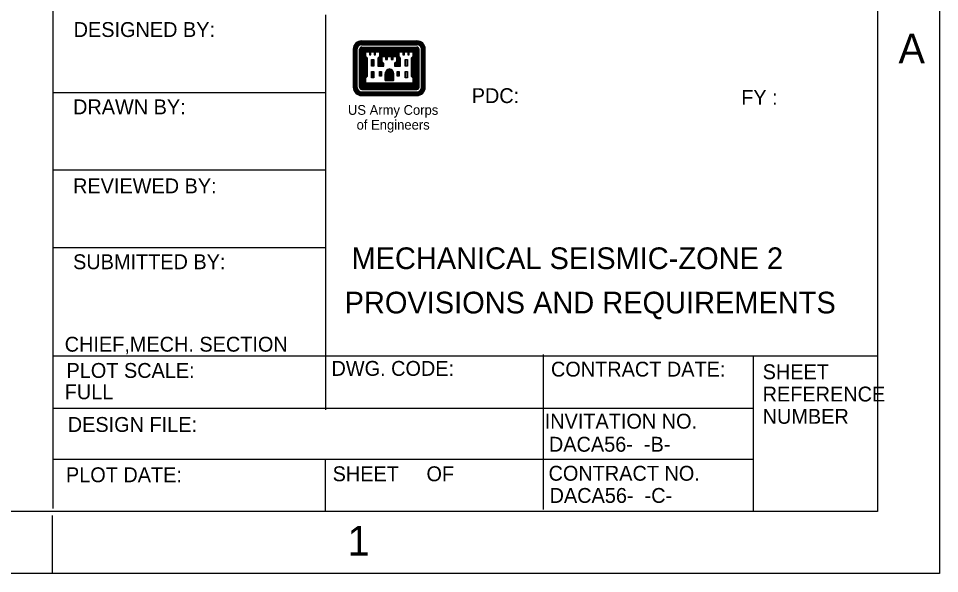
# Model space of a CAD drawing. Extents: x 9999.96 to 10005.26, y 9999.88 to 10002.38.
# Drawn here: x 10002.841 to 10003.46, y 9999.885 to 10000.258 of the extents above; entities that cross this region are included whole.
import ezdxf

# ---------------------------------------------------------------- set-up
doc = ezdxf.new("R2010")
doc.units = 0
for name, color, linetype in [('Level 1', 7, 'Continuous'), ('Level 3', 7, 'Continuous'), ('Level 50', 7, 'Continuous'), ('Level 6', 7, 'Continuous')]:
    doc.layers.add(name, color=color, linetype=linetype)

msp = doc.modelspace()

# ---------------------------------------------------------------- linework, layer by layer
at = {"layer": 'Level 1'}
for p, q in [((10003.46033, 10002.38453), (10003.46033, 9999.88453)), ((10003.41867, 10002.34286), (10003.41867, 9999.9262)), ((10002.86401, 9999.92827), (10002.86401, 10000.35495)), ((10003.04708, 10000.26011), (10003.04708, 9999.9945)), ((10002.86401, 10000.20803), (10003.04708, 10000.20803)), ((10002.86401, 10000.15595), (10003.04708, 10000.15595)), ((10002.86401, 10000.10386), (10003.04708, 10000.10386)), ((10002.86401, 10000.03095), (10003.41867, 10000.03095)), ((10003.19381, 9999.92764), (10003.19381, 10000.0318)), ((10003.3352, 9999.92626), (10003.3352, 10000.03043)), ((10002.86401, 9999.99561), (10003.3352, 9999.99561)), ((10003.3352, 9999.9612), (10002.86401, 9999.9612)), ((10003.04708, 9999.92678), (10003.04708, 9999.96068)), ((10003.41867, 9999.9262), (10000.127, 9999.9262)), ((10002.8635, 9999.8845), (10002.8635, 9999.92348)), ((10003.46033, 9999.88453), (9999.96033, 9999.88453))]:
    msp.add_line(p, q, dxfattribs=at)
at = {"layer": 'Level 6'}
for p, q in [((10003.07063, 10000.23997), (10003.07063, 10000.24268)), ((10003.07135, 10000.24008), (10003.07135, 10000.24268)), ((10003.07152, 10000.24273), (10003.10871, 10000.24273)), ((10003.07203, 10000.24008), (10003.07203, 10000.24268)), ((10003.07276, 10000.24008), (10003.07276, 10000.24268)), ((10003.07344, 10000.24008), (10003.07344, 10000.24268)), ((10003.07417, 10000.24008), (10003.07417, 10000.24268)), ((10003.07484, 10000.24008), (10003.07484, 10000.24268)), ((10003.07557, 10000.24008), (10003.07557, 10000.24268)), ((10003.07624, 10000.24008), (10003.07624, 10000.24268)), ((10003.07697, 10000.24008), (10003.07697, 10000.24268)), ((10003.07765, 10000.24008), (10003.07765, 10000.24268)), ((10003.07838, 10000.24008), (10003.07838, 10000.24268)), ((10003.07905, 10000.24008), (10003.07905, 10000.24268)), ((10003.07978, 10000.24008), (10003.07978, 10000.24268)), ((10003.08045, 10000.24008), (10003.08045, 10000.24268)), ((10003.08118, 10000.24008), (10003.08118, 10000.24268)), ((10003.08185, 10000.24008), (10003.08185, 10000.24268)), ((10003.08258, 10000.24008), (10003.08258, 10000.24268)), ((10003.08326, 10000.24008), (10003.08326, 10000.24268)), ((10003.08399, 10000.24008), (10003.08399, 10000.24268)), ((10003.08466, 10000.24008), (10003.08466, 10000.24268)), ((10003.08539, 10000.24008), (10003.08539, 10000.24268)), ((10003.08606, 10000.24008), (10003.08606, 10000.24268)), ((10003.08679, 10000.24008), (10003.08679, 10000.24268)), ((10003.08747, 10000.24008), (10003.08747, 10000.24268)), ((10003.0882, 10000.24008), (10003.0882, 10000.24268)), ((10003.08888, 10000.24008), (10003.08888, 10000.24268)), ((10003.0896, 10000.24008), (10003.0896, 10000.24268)), ((10003.09028, 10000.24008), (10003.09028, 10000.24268)), ((10003.09101, 10000.24008), (10003.09101, 10000.24268)), ((10003.09169, 10000.24008), (10003.09169, 10000.24268)), ((10003.09242, 10000.24008), (10003.09242, 10000.24268)), ((10003.09309, 10000.24008), (10003.09309, 10000.24268)), ((10003.09381, 10000.24008), (10003.09381, 10000.24268)), ((10003.09449, 10000.24008), (10003.09449, 10000.24268)), ((10003.09522, 10000.24008), (10003.09522, 10000.24268)), ((10003.0959, 10000.24008), (10003.0959, 10000.24268)), ((10003.09663, 10000.24008), (10003.09663, 10000.24268)), ((10003.0973, 10000.24008), (10003.0973, 10000.24268)), ((10003.09802, 10000.24008), (10003.09802, 10000.24268)), ((10003.0987, 10000.24008), (10003.0987, 10000.24268)), ((10003.09943, 10000.24008), (10003.09943, 10000.24268)), ((10003.1001, 10000.24008), (10003.1001, 10000.24268)), ((10003.10083, 10000.24008), (10003.10083, 10000.24268)), ((10003.10151, 10000.24008), (10003.10151, 10000.24268)), ((10003.10224, 10000.24008), (10003.10224, 10000.24268)), ((10003.10291, 10000.24008), (10003.10291, 10000.24268)), ((10003.10365, 10000.24008), (10003.10365, 10000.24268)), ((10003.10431, 10000.24008), (10003.10431, 10000.24268)), ((10003.10505, 10000.24008), (10003.10505, 10000.24268)), ((10003.10572, 10000.24008), (10003.10572, 10000.24268)), ((10003.10646, 10000.24008), (10003.10646, 10000.24268)), ((10003.10713, 10000.24008), (10003.10713, 10000.24268)), ((10003.10786, 10000.24008), (10003.10786, 10000.24268)), ((10003.10853, 10000.24008), (10003.10853, 10000.24268)), ((10003.10927, 10000.24008), (10003.10927, 10000.24268)), ((10003.10994, 10000.23986), (10003.10994, 10000.24261)), ((10003.06591, 10000.2115), (10003.06591, 10000.23711)), ((10003.06642, 10000.2092), (10003.06642, 10000.23941)), ((10003.06714, 10000.20796), (10003.06714, 10000.24065)), ((10003.06781, 10000.20729), (10003.06781, 10000.24132)), ((10003.06854, 10000.23728), (10003.06854, 10000.24189)), ((10003.06854, 10000.21133), (10003.06854, 10000.23728)), ((10003.06922, 10000.23907), (10003.06922, 10000.24222)), ((10003.06995, 10000.23969), (10003.06995, 10000.2425)), ((10003.07011, 10000.2115), (10003.07011, 10000.23711)), ((10003.07063, 10000.21044), (10003.07063, 10000.23819)), ((10003.07135, 10000.24008), (10003.10888, 10000.24008)), ((10003.07135, 10000.21009), (10003.07135, 10000.23852)), ((10003.07152, 10000.23852), (10003.10871, 10000.23852)), ((10003.07203, 10000.21009), (10003.07203, 10000.23852)), ((10003.07276, 10000.21009), (10003.07276, 10000.23852)), ((10003.07344, 10000.21009), (10003.07344, 10000.23852)), ((10003.07417, 10000.21009), (10003.07417, 10000.23852)), ((10003.07484, 10000.23538), (10003.07484, 10000.23852)), ((10003.07557, 10000.23538), (10003.07557, 10000.23852)), ((10003.07624, 10000.23538), (10003.07624, 10000.23852)), ((10003.07697, 10000.23323), (10003.07697, 10000.23852)), ((10003.07765, 10000.23323), (10003.07765, 10000.23852)), ((10003.07838, 10000.23538), (10003.07838, 10000.23852)), ((10003.07905, 10000.23538), (10003.07905, 10000.23852)), ((10003.07978, 10000.23538), (10003.07978, 10000.23852)), ((10003.08045, 10000.23329), (10003.08045, 10000.23852)), ((10003.08118, 10000.23538), (10003.08118, 10000.23852)), ((10003.08185, 10000.23538), (10003.08185, 10000.23852)), ((10003.08258, 10000.23538), (10003.08258, 10000.23852)), ((10003.08326, 10000.23538), (10003.08326, 10000.23852)), ((10003.08399, 10000.22559), (10003.08399, 10000.23852)), ((10003.08466, 10000.22559), (10003.08466, 10000.23852)), ((10003.08539, 10000.23222), (10003.08539, 10000.23852)), ((10003.08606, 10000.23222), (10003.08606, 10000.23852)), ((10003.08679, 10000.23222), (10003.08679, 10000.23852)), ((10003.08747, 10000.23222), (10003.08747, 10000.23852)), ((10003.0882, 10000.23008), (10003.0882, 10000.23852)), ((10003.08888, 10000.23222), (10003.08888, 10000.23852)), ((10003.0896, 10000.23222), (10003.0896, 10000.23852)), ((10003.09028, 10000.23222), (10003.09028, 10000.23852)), ((10003.09101, 10000.23222), (10003.09101, 10000.23852)), ((10003.09169, 10000.23008), (10003.09169, 10000.23852)), ((10003.09242, 10000.23008), (10003.09242, 10000.23852)), ((10003.09309, 10000.23222), (10003.09309, 10000.23852)), ((10003.09381, 10000.23222), (10003.09381, 10000.23852)), ((10003.09381, 10000.23222), (10003.09381, 10000.23852)), ((10003.09449, 10000.23222), (10003.09449, 10000.23852)), ((10003.09522, 10000.22559), (10003.09522, 10000.23852)), ((10003.0959, 10000.22559), (10003.0959, 10000.23852)), ((10003.09663, 10000.22559), (10003.09663, 10000.23852)), ((10003.0973, 10000.23538), (10003.0973, 10000.23852)), ((10003.09802, 10000.23538), (10003.09802, 10000.23852)), ((10003.0987, 10000.23538), (10003.0987, 10000.23852)), ((10003.09943, 10000.23323), (10003.09943, 10000.23852)), ((10003.1001, 10000.23323), (10003.1001, 10000.23852)), ((10003.10083, 10000.23538), (10003.10083, 10000.23852)), ((10003.10157, 10000.23538), (10003.10157, 10000.23852)), ((10003.10224, 10000.23538), (10003.10224, 10000.23852)), ((10003.10291, 10000.23323), (10003.10291, 10000.23852)), ((10003.10365, 10000.23538), (10003.10365, 10000.23852)), ((10003.10431, 10000.23538), (10003.10431, 10000.23852)), ((10003.10505, 10000.23538), (10003.10505, 10000.23852)), ((10003.10572, 10000.23538), (10003.10572, 10000.23852)), ((10003.10646, 10000.21009), (10003.10646, 10000.23852)), ((10003.10713, 10000.21009), (10003.10713, 10000.23852)), ((10003.10786, 10000.21009), (10003.10786, 10000.23852)), ((10003.10853, 10000.21009), (10003.10853, 10000.23852)), ((10003.10927, 10000.21021), (10003.10927, 10000.23841)), ((10003.10994, 10000.21082), (10003.10994, 10000.23779)), ((10003.11011, 10000.2115), (10003.11011, 10000.23711)), ((10003.11068, 10000.23941), (10003.11068, 10000.2424)), ((10003.11133, 10000.23863), (10003.11133, 10000.24205)), ((10003.11168, 10000.21133), (10003.11168, 10000.23728)), ((10003.11207, 10000.20701), (10003.11207, 10000.2416)), ((10003.1128, 10000.20769), (10003.1128, 10000.24093)), ((10003.11348, 10000.20852), (10003.11348, 10000.24008)), ((10003.11421, 10000.21038), (10003.11421, 10000.23824)), ((10003.11432, 10000.2115), (10003.11432, 10000.23711)), ((10003.07433, 10000.23222), (10003.07433, 10000.23538)), ((10003.07433, 10000.23538), (10003.07669, 10000.23538)), ((10003.07433, 10000.23222), (10003.07433, 10000.23538)), ((10003.07433, 10000.23538), (10003.07669, 10000.23538)), ((10003.07541, 10000.23116), (10003.07433, 10000.23222)), ((10003.07541, 10000.23116), (10003.07433, 10000.23222)), ((10003.0749, 10000.21841), (10003.0749, 10000.23166)), ((10003.07541, 10000.21903), (10003.07541, 10000.23116)), ((10003.07541, 10000.21903), (10003.07541, 10000.23116)), ((10003.07669, 10000.23538), (10003.07669, 10000.23323)), ((10003.07669, 10000.23538), (10003.07669, 10000.23323)), ((10003.07669, 10000.23323), (10003.07776, 10000.23323)), ((10003.07669, 10000.23323), (10003.07776, 10000.23323)), ((10003.07776, 10000.23323), (10003.07776, 10000.23538)), ((10003.07776, 10000.23538), (10003.0799, 10000.23538)), ((10003.07776, 10000.23323), (10003.07776, 10000.23538)), ((10003.07776, 10000.23538), (10003.0799, 10000.23538)), ((10003.0799, 10000.23538), (10003.0799, 10000.23323)), ((10003.0799, 10000.23538), (10003.0799, 10000.23323)), ((10003.0799, 10000.23323), (10003.0809, 10000.23323)), ((10003.0799, 10000.23323), (10003.0809, 10000.23323)), ((10003.0809, 10000.23323), (10003.0809, 10000.23538)), ((10003.0809, 10000.23538), (10003.08354, 10000.23538)), ((10003.0809, 10000.23323), (10003.0809, 10000.23538)), ((10003.0809, 10000.23538), (10003.08354, 10000.23538)), ((10003.08354, 10000.23222), (10003.08247, 10000.23116)), ((10003.08354, 10000.23222), (10003.08247, 10000.23116)), ((10003.08247, 10000.23116), (10003.08247, 10000.22559)), ((10003.08247, 10000.23116), (10003.08247, 10000.22559)), ((10003.08258, 10000.22559), (10003.08258, 10000.23126)), ((10003.08331, 10000.22559), (10003.08331, 10000.232)), ((10003.08354, 10000.23538), (10003.08354, 10000.23222)), ((10003.08354, 10000.23538), (10003.08354, 10000.23222)), ((10003.08539, 10000.22852), (10003.08539, 10000.23222)), ((10003.08539, 10000.23222), (10003.08747, 10000.23222)), ((10003.08747, 10000.23222), (10003.08747, 10000.23008)), ((10003.08882, 10000.23008), (10003.08882, 10000.23222)), ((10003.08882, 10000.23222), (10003.09146, 10000.23222)), ((10003.09146, 10000.23222), (10003.09146, 10000.23008)), ((10003.09276, 10000.23008), (10003.09276, 10000.23222)), ((10003.09276, 10000.23222), (10003.09489, 10000.23222)), ((10003.09489, 10000.23222), (10003.09489, 10000.22852)), ((10003.09674, 10000.23222), (10003.09674, 10000.23538)), ((10003.09674, 10000.23538), (10003.09932, 10000.23538)), ((10003.09774, 10000.23116), (10003.09674, 10000.23222)), ((10003.09736, 10000.22559), (10003.09736, 10000.23154)), ((10003.09774, 10000.22559), (10003.09774, 10000.23116)), ((10003.09932, 10000.23538), (10003.09932, 10000.23323)), ((10003.09932, 10000.23323), (10003.10039, 10000.23323)), ((10003.10039, 10000.23323), (10003.10039, 10000.23538)), ((10003.10039, 10000.23538), (10003.10252, 10000.23538)), ((10003.10252, 10000.23538), (10003.10252, 10000.23323)), ((10003.10252, 10000.23323), (10003.10353, 10000.23323)), ((10003.10353, 10000.23323), (10003.10353, 10000.23538)), ((10003.10353, 10000.23538), (10003.10595, 10000.23538)), ((10003.10595, 10000.23222), (10003.10488, 10000.23116)), ((10003.10488, 10000.23116), (10003.10488, 10000.21903)), ((10003.10505, 10000.21886), (10003.10505, 10000.23132)), ((10003.10572, 10000.21819), (10003.10572, 10000.232)), ((10003.10595, 10000.23538), (10003.10595, 10000.23222)), ((10003.07804, 10000.22559), (10003.07804, 10000.23008)), ((10003.07804, 10000.23008), (10003.07961, 10000.23008)), ((10003.07961, 10000.22559), (10003.07804, 10000.22559)), ((10003.07838, 10000.22559), (10003.07838, 10000.23008)), ((10003.07905, 10000.22559), (10003.07905, 10000.23008)), ((10003.07961, 10000.23008), (10003.07961, 10000.22559)), ((10003.08247, 10000.22559), (10003.08646, 10000.22559)), ((10003.08247, 10000.22559), (10003.08646, 10000.22559)), ((10003.08539, 10000.22559), (10003.08539, 10000.22852)), ((10003.08646, 10000.22745), (10003.08539, 10000.22852)), ((10003.08606, 10000.22559), (10003.08606, 10000.22784)), ((10003.08646, 10000.22559), (10003.08646, 10000.22745)), ((10003.08747, 10000.23008), (10003.08882, 10000.23008)), ((10003.09146, 10000.23008), (10003.09276, 10000.23008)), ((10003.09489, 10000.22852), (10003.09353, 10000.22745)), ((10003.09353, 10000.22745), (10003.09353, 10000.22559)), ((10003.09353, 10000.22559), (10003.09774, 10000.22559)), ((10003.09381, 10000.22559), (10003.09381, 10000.22768)), ((10003.09455, 10000.22559), (10003.09455, 10000.22824)), ((10003.10067, 10000.22559), (10003.10067, 10000.23008)), ((10003.10067, 10000.23008), (10003.10224, 10000.23008)), ((10003.10224, 10000.22559), (10003.10067, 10000.22559)), ((10003.10083, 10000.22559), (10003.10083, 10000.23008)), ((10003.10151, 10000.22559), (10003.10151, 10000.23008)), ((10003.10224, 10000.23008), (10003.10224, 10000.22559)), ((10003.07433, 10000.21774), (10003.07541, 10000.21903)), ((10003.07433, 10000.21774), (10003.07541, 10000.21903)), ((10003.07804, 10000.21796), (10003.07804, 10000.22217)), ((10003.07804, 10000.22217), (10003.07961, 10000.22217)), ((10003.07961, 10000.21796), (10003.07804, 10000.21796)), ((10003.07838, 10000.21796), (10003.07838, 10000.22217)), ((10003.07905, 10000.21796), (10003.07905, 10000.22217)), ((10003.07961, 10000.22217), (10003.07961, 10000.21796)), ((10003.08354, 10000.21903), (10003.08354, 10000.22217)), ((10003.08354, 10000.22217), (10003.08489, 10000.22217)), ((10003.08489, 10000.21903), (10003.08354, 10000.21903)), ((10003.08399, 10000.21903), (10003.08399, 10000.22217)), ((10003.08466, 10000.21903), (10003.08466, 10000.22217)), ((10003.08489, 10000.22217), (10003.08489, 10000.21903)), ((10003.08724, 10000.21616), (10003.08724, 10000.2206)), ((10003.08747, 10000.21616), (10003.08747, 10000.22172)), ((10003.0882, 10000.21616), (10003.0882, 10000.22279)), ((10003.08888, 10000.21616), (10003.08888, 10000.22335)), ((10003.0896, 10000.21616), (10003.0896, 10000.22369)), ((10003.09028, 10000.21616), (10003.09028, 10000.2238)), ((10003.09101, 10000.21616), (10003.09101, 10000.22357)), ((10003.09169, 10000.21616), (10003.09169, 10000.22319)), ((10003.09242, 10000.21616), (10003.09242, 10000.22251)), ((10003.09309, 10000.21616), (10003.09309, 10000.2206)), ((10003.0954, 10000.21903), (10003.0954, 10000.22217)), ((10003.0954, 10000.22217), (10003.09674, 10000.22217)), ((10003.09674, 10000.21903), (10003.0954, 10000.21903)), ((10003.0959, 10000.21903), (10003.0959, 10000.22217)), ((10003.09663, 10000.21903), (10003.09663, 10000.22217)), ((10003.09674, 10000.22217), (10003.09674, 10000.21903)), ((10003.10067, 10000.21796), (10003.10067, 10000.22217)), ((10003.10067, 10000.22217), (10003.10224, 10000.22217)), ((10003.10224, 10000.21796), (10003.10067, 10000.21796)), ((10003.10083, 10000.21796), (10003.10083, 10000.22217)), ((10003.10151, 10000.21796), (10003.10151, 10000.22217)), ((10003.10224, 10000.22217), (10003.10224, 10000.21796)), ((10003.10488, 10000.21903), (10003.10595, 10000.21796)), ((10003.10595, 10000.21796), (10003.10595, 10000.2143)), ((10003.07433, 10000.2143), (10003.07433, 10000.21774)), ((10003.07433, 10000.2143), (10003.07433, 10000.21774)), ((10003.10595, 10000.2143), (10003.07433, 10000.2143)), ((10003.07484, 10000.21009), (10003.07484, 10000.2143)), ((10003.07557, 10000.21009), (10003.07557, 10000.2143)), ((10003.07624, 10000.21009), (10003.07624, 10000.2143)), ((10003.07697, 10000.21009), (10003.07697, 10000.2143)), ((10003.07765, 10000.21009), (10003.07765, 10000.2143)), ((10003.07838, 10000.21009), (10003.07838, 10000.2143)), ((10003.07905, 10000.21009), (10003.07905, 10000.2143)), ((10003.07978, 10000.21009), (10003.07978, 10000.2143)), ((10003.08045, 10000.21009), (10003.08045, 10000.2143)), ((10003.08118, 10000.21009), (10003.08118, 10000.2143)), ((10003.08185, 10000.21009), (10003.08185, 10000.2143)), ((10003.08258, 10000.21009), (10003.08258, 10000.2143)), ((10003.08326, 10000.21009), (10003.08326, 10000.2143)), ((10003.08399, 10000.21009), (10003.08399, 10000.2143)), ((10003.08466, 10000.21009), (10003.08466, 10000.2143)), ((10003.08539, 10000.21009), (10003.08539, 10000.2143)), ((10003.08606, 10000.21009), (10003.08606, 10000.2143)), ((10003.08679, 10000.21009), (10003.08679, 10000.2143)), ((10003.09309, 10000.21616), (10003.08724, 10000.21616)), ((10003.08724, 10000.21616), (10003.09304, 10000.21616)), ((10003.08747, 10000.21009), (10003.08747, 10000.2143)), ((10003.0882, 10000.21009), (10003.0882, 10000.2143)), ((10003.08888, 10000.21009), (10003.08888, 10000.2143)), ((10003.0896, 10000.21009), (10003.0896, 10000.2143)), ((10003.09028, 10000.21009), (10003.09028, 10000.2143)), ((10003.09101, 10000.21009), (10003.09101, 10000.2143)), ((10003.09169, 10000.21009), (10003.09169, 10000.2143)), ((10003.09242, 10000.21009), (10003.09242, 10000.2143)), ((10003.09309, 10000.21009), (10003.09309, 10000.2143)), ((10003.09381, 10000.21009), (10003.09381, 10000.2143)), ((10003.09449, 10000.21009), (10003.09449, 10000.2143)), ((10003.09522, 10000.21009), (10003.09522, 10000.2143)), ((10003.0959, 10000.21009), (10003.0959, 10000.2143)), ((10003.09663, 10000.21009), (10003.09663, 10000.2143)), ((10003.0973, 10000.21009), (10003.0973, 10000.2143)), ((10003.09802, 10000.21009), (10003.09802, 10000.2143)), ((10003.0987, 10000.21009), (10003.0987, 10000.2143)), ((10003.09943, 10000.21009), (10003.09943, 10000.2143)), ((10003.1001, 10000.21009), (10003.1001, 10000.2143)), ((10003.10083, 10000.21009), (10003.10083, 10000.2143)), ((10003.10151, 10000.21009), (10003.10151, 10000.2143)), ((10003.10224, 10000.21009), (10003.10224, 10000.2143)), ((10003.10291, 10000.21009), (10003.10291, 10000.2143)), ((10003.10365, 10000.21009), (10003.10365, 10000.2143)), ((10003.10431, 10000.21009), (10003.10431, 10000.2143)), ((10003.10505, 10000.21009), (10003.10505, 10000.2143)), ((10003.10572, 10000.21009), (10003.10572, 10000.2143)), ((10003.06854, 10000.20673), (10003.06854, 10000.21133)), ((10003.06922, 10000.2064), (10003.06922, 10000.20953)), ((10003.06995, 10000.20611), (10003.06995, 10000.20892)), ((10003.07063, 10000.20594), (10003.07063, 10000.20864)), ((10003.07135, 10000.20852), (10003.10888, 10000.20852)), ((10003.07135, 10000.20594), (10003.07135, 10000.20852)), ((10003.07152, 10000.21009), (10003.10871, 10000.21009)), ((10003.07152, 10000.20589), (10003.10871, 10000.20589)), ((10003.07203, 10000.20594), (10003.07203, 10000.20852)), ((10003.07276, 10000.20594), (10003.07276, 10000.20852)), ((10003.07344, 10000.20594), (10003.07344, 10000.20852)), ((10003.07417, 10000.20594), (10003.07417, 10000.20852)), ((10003.07484, 10000.20594), (10003.07484, 10000.20852)), ((10003.07557, 10000.20594), (10003.07557, 10000.20852)), ((10003.07624, 10000.20594), (10003.07624, 10000.20852)), ((10003.07697, 10000.20594), (10003.07697, 10000.20852)), ((10003.07765, 10000.20594), (10003.07765, 10000.20852)), ((10003.07838, 10000.20594), (10003.07838, 10000.20852)), ((10003.07905, 10000.20594), (10003.07905, 10000.20852)), ((10003.07978, 10000.20594), (10003.07978, 10000.20852)), ((10003.08045, 10000.20594), (10003.08045, 10000.20852)), ((10003.08118, 10000.20594), (10003.08118, 10000.20852)), ((10003.08185, 10000.20594), (10003.08185, 10000.20852)), ((10003.08258, 10000.20594), (10003.08258, 10000.20852)), ((10003.08326, 10000.20594), (10003.08326, 10000.20852)), ((10003.08399, 10000.20594), (10003.08399, 10000.20852)), ((10003.08466, 10000.20594), (10003.08466, 10000.20852)), ((10003.08539, 10000.20594), (10003.08539, 10000.20852)), ((10003.08606, 10000.20594), (10003.08606, 10000.20852)), ((10003.08679, 10000.20594), (10003.08679, 10000.20852)), ((10003.08747, 10000.20594), (10003.08747, 10000.20852)), ((10003.0882, 10000.20594), (10003.0882, 10000.20852)), ((10003.08888, 10000.20594), (10003.08888, 10000.20852)), ((10003.0896, 10000.20594), (10003.0896, 10000.20852)), ((10003.09028, 10000.20594), (10003.09028, 10000.20852)), ((10003.09101, 10000.20594), (10003.09101, 10000.20852)), ((10003.09169, 10000.20594), (10003.09169, 10000.20852)), ((10003.09242, 10000.20594), (10003.09242, 10000.20852)), ((10003.09309, 10000.20594), (10003.09309, 10000.20852)), ((10003.09381, 10000.20594), (10003.09381, 10000.20852)), ((10003.09449, 10000.20594), (10003.09449, 10000.20852)), ((10003.09522, 10000.20594), (10003.09522, 10000.20852)), ((10003.0959, 10000.20594), (10003.0959, 10000.20852)), ((10003.09663, 10000.20594), (10003.09663, 10000.20852)), ((10003.0973, 10000.20594), (10003.0973, 10000.20852)), ((10003.09802, 10000.20594), (10003.09802, 10000.20852)), ((10003.0987, 10000.20594), (10003.0987, 10000.20852)), ((10003.09943, 10000.20594), (10003.09943, 10000.20852)), ((10003.1001, 10000.20594), (10003.1001, 10000.20852)), ((10003.10083, 10000.20594), (10003.10083, 10000.20852)), ((10003.10151, 10000.20594), (10003.10151, 10000.20852)), ((10003.10224, 10000.20594), (10003.10224, 10000.20852)), ((10003.10291, 10000.20594), (10003.10291, 10000.20852)), ((10003.10365, 10000.20594), (10003.10365, 10000.20852)), ((10003.10431, 10000.20594), (10003.10431, 10000.20852)), ((10003.10505, 10000.20594), (10003.10505, 10000.20852)), ((10003.10572, 10000.20594), (10003.10572, 10000.20852)), ((10003.10646, 10000.20594), (10003.10646, 10000.20852)), ((10003.10713, 10000.20594), (10003.10713, 10000.20852)), ((10003.10786, 10000.20594), (10003.10786, 10000.20852)), ((10003.10853, 10000.20594), (10003.10853, 10000.20852)), ((10003.10927, 10000.20594), (10003.10927, 10000.20852)), ((10003.10994, 10000.206), (10003.10994, 10000.20875)), ((10003.11068, 10000.20622), (10003.11068, 10000.2092)), ((10003.11133, 10000.20656), (10003.11133, 10000.20998))]:
    msp.add_line(p, q, dxfattribs=at)
for centre, radius, start, end in [((10003.07152, 10000.23711), 0.00562, 90, 180), ((10003.1087, 10000.23711), 0.00562, 0, 90), ((10003.07136, 10000.23728), 0.00281, 90, 180), ((10003.07152, 10000.23711), 0.0014, 90, 180), ((10003.1087, 10000.23711), 0.0014, 0, 90), ((10003.10887, 10000.23728), 0.00281, 0, 90), ((10003.09063, 10000.22043), 0.0034, 97.72175, 177.14315), ((10003.08971, 10000.22043), 0.0034, 2.85685, 82.27825), ((10003.07152, 10000.2115), 0.00562, 180, 270), ((10003.07136, 10000.21133), 0.00281, 180, 270), ((10003.07152, 10000.2115), 0.0014, 180, 270), ((10003.1087, 10000.2115), 0.00562, 270, 0), ((10003.1087, 10000.2115), 0.0014, 270, 0), ((10003.10887, 10000.21133), 0.00281, 270, 0)]:
    msp.add_arc(centre, radius, start, end, dxfattribs=at)

# ---------------------------------------------------------------- texts
at = {"layer": 'Level 1'}
for s, height, p in [('DESIGNED BY:', 0.01, (10002.87774, 10000.24532)), ('A', 0.02, (10003.43267, 10000.22753)), ('PDC:', 0.009984, (10003.14558, 10000.20089)), ('FY :', 0.009984, (10003.32688, 10000.19973)), ('DRAWN BY:', 0.01, (10002.87734, 10000.19334)), ('REVIEWED BY:', 0.01, (10002.87734, 10000.14021)), ('SUBMITTED BY:', 0.01, (10002.87734, 10000.08917)), ('PLOT SCALE:', 0.01, (10002.87293, 10000.01608)), ('DWG. CODE:', 0.01, (10003.05121, 10000.01746)), ('CONTRACT DATE:', 0.01, (10003.19888, 10000.01695)), ('SHEET', 0.01, (10003.3413, 10000.01521)), ('REFERENCE', 0.01, (10003.3413, 10000.00021)), ('NUMBER', 0.01, (10003.3413, 9999.98521)), ('DESIGN FILE:', 0.01, (10002.87378, 9999.97976)), ('INVITATION NO.', 0.01, (10003.19465, 9999.98195)), ('DACA56-  -B-    ', 0.01, (10003.19752, 9999.96645)), ('PLOT DATE:', 0.01, (10002.87256, 9999.94593)), ('SHEET     OF', 0.01, (10003.05196, 9999.9466)), ('CONTRACT NO.', 0.01, (10003.19725, 9999.94694)), ('DACA56-  -C-    ', 0.01, (10003.19795, 9999.93203)), ('1', 0.02, (10003.062, 9999.89653))]:
    msp.add_text(s, height=height, dxfattribs=at).set_placement(p)
at = {"layer": 'Level 3'}
for s, height, p in [('   MECHANICAL SEISMIC-ZONE 2   ', 0.0145816, (10003.04841, 10000.08924)), ('  PROVISIONS AND REQUIREMENTS  ', 0.0145833, (10003.0492, 10000.05943)), ('CHIEF,MECH. SECTION', 0.01, (10002.87172, 10000.03372)), ('FULL              ', 0.0100011, (10002.87172, 10000.00174))]:
    msp.add_text(s, height=height, dxfattribs=at).set_placement(p)
at = {"layer": 'Level 50'}
for s, p in [('US Army Corps', (10003.06226, 10000.19298)), ('of Engineers', (10003.06811, 10000.18302))]:
    msp.add_text(s, height=0.0065473, dxfattribs=at).set_placement(p)

doc.saveas('drawing.dxf')
